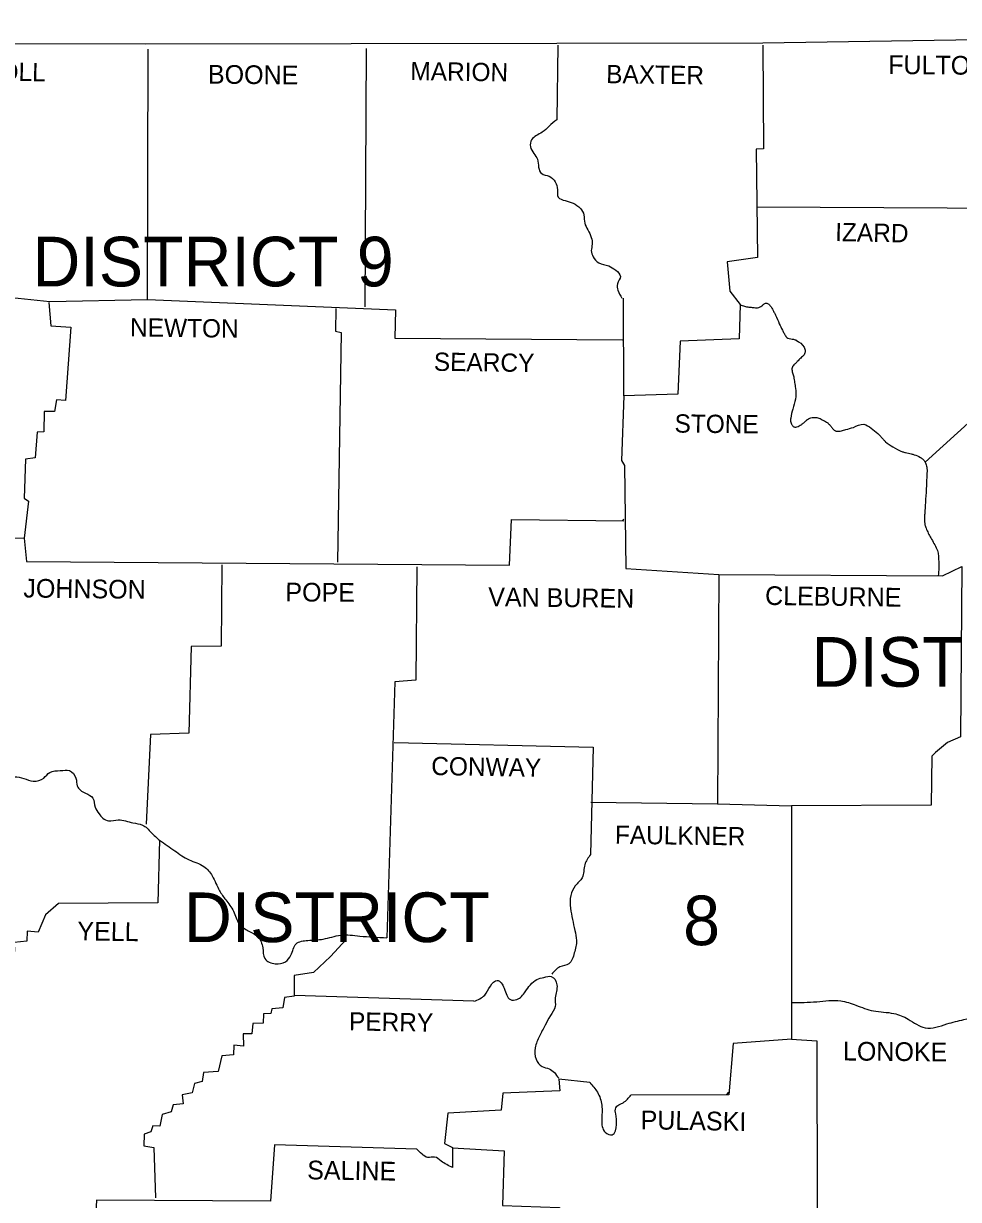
# Model space of a CAD drawing. Extents: x 3046 to 131673, y -8885 to 10756.
# Drawn here: x 103075 to 105176, y 7714 to 10358 of the extents above; entities that cross this region are included whole.
import ezdxf

# ---------------------------------------------------------------- set-up
doc = ezdxf.new("R2010")
doc.units = 0
for name, color, linetype in [('1', 7, 'Continuous'), ('2', 7, 'Continuous'), ('3', 7, 'Continuous')]:
    doc.layers.add(name, color=color, linetype=linetype)

msp = doc.modelspace()

# ---------------------------------------------------------------- linework, layer by layer
at = {"layer": '1'}
for points in [[(101766.1, 10313), (103348.2, 10312), (104736.6, 10314.9), (106374.4, 10340.4), (107133.7, 10358)], [(101766.1, 10313), (103348.2, 10312), (104736.6, 10314.9), (106374.4, 10340.4), (107133.7, 10358)], [(105565.2, 10327.8), (105567.2, 10081.1), (105440, 10074.3), (105436.1, 9941.2), (104723.5, 9945.1)], [(105565.2, 10327.8), (105567.2, 10081.1), (105440, 10074.3), (105436.1, 9941.2), (104723.5, 9945.1)], [(102667.2, 10007.7), (102907.9, 9999.9), (102913.8, 9968.6), (102947.1, 9967.6), (102946.1, 9948), (102969.6, 9942.2), (102971.5, 9835.5), (103001.9, 9828.7), (103003.8, 9786.6), (103046.9, 9780.7), (103048.8, 9741.6), (103133.9, 9732.8), (103353.1, 9737.7), (103355.1, 10300.3)], [(102667.2, 10007.7), (102907.9, 9999.9), (102913.8, 9968.6), (102947.1, 9967.6), (102946.1, 9948), (102969.6, 9942.2), (102971.5, 9835.5), (103001.9, 9828.7), (103003.8, 9786.6), (103046.9, 9780.7), (103048.8, 9741.6), (103133.9, 9732.8), (103353.1, 9737.7), (103355.1, 10300.3)], [(103845.2, 10302.2), (103842.3, 9721.1)], [(103845.2, 10302.2), (103842.3, 9721.1)], [(104275.7, 10309.1), (104273.8, 10141.8)], [(104275.7, 10309.1), (104273.8, 10141.8)], [(104736.6, 10309.1), (104738.5, 10076.2), (104721.9, 10075.2), (104724.8, 9831.6), (104656.3, 9821.8), (104662.2, 9756.3), (104685.7, 9725.9), (104683.7, 9648.7), (104550.7, 9643.8), (104545.8, 9524.4), (104424.5, 9520.5), (104418.6, 9375.7), (104425.4, 9363.9), (104428.4, 9133), (104637.7, 9119.3), (104634.8, 8603.7), (104801.1, 8598.8), (104801.1, 8074.4), (104670, 8064.6), (104660.3, 7949.2), (104440.1, 7948.2)], [(104736.6, 10309.1), (104738.5, 10076.2), (104721.9, 10075.2), (104724.8, 9831.6), (104656.3, 9821.8), (104662.2, 9756.3), (104685.7, 9725.9), (104683.7, 9648.7), (104550.7, 9643.8), (104545.8, 9524.4), (104424.5, 9520.5), (104418.6, 9375.7), (104425.4, 9363.9), (104428.4, 9133), (104637.7, 9119.3), (104634.8, 8603.7), (104801.1, 8598.8), (104801.1, 8074.4), (104670, 8064.6), (104660.3, 7949.2), (104440.1, 7948.2)], [(101843.4, 9721.1), (102026.4, 9720.1), (102031.3, 9784.6), (102098.8, 9784.6), (102104.7, 9889.3), (102486.2, 9875.6), (102498, 9905), (102655.5, 9906), (102576.2, 9679), (102560.6, 9316), (102548.9, 9315), (102543, 9205.4), (102600.7, 9200.5), (102609.5, 9209.3), (103076.2, 9200.5), (103081.1, 9148.7)], [(101843.4, 9721.1), (102026.4, 9720.1), (102031.3, 9784.6), (102098.8, 9784.6), (102104.7, 9889.3), (102486.2, 9875.6), (102498, 9905), (102655.5, 9906), (102576.2, 9679), (102560.6, 9316), (102548.9, 9315), (102543, 9205.4), (102600.7, 9200.5), (102609.5, 9209.3), (103076.2, 9200.5), (103081.1, 9148.7)], [(103132, 9730.8), (103135.9, 9678), (103180.9, 9675.1), (103169.2, 9510.7), (103148.6, 9511.7), (103144.7, 9485.3), (103121.2, 9485.3), (103120.2, 9440.2), (103105.6, 9439.3), (103100.7, 9381.5), (103079.1, 9378.6), (103076.2, 9290.6), (103086, 9283.7), (103076.2, 9200.5)], [(103132, 9730.8), (103135.9, 9678), (103180.9, 9675.1), (103169.2, 9510.7), (103148.6, 9511.7), (103144.7, 9485.3), (103121.2, 9485.3), (103120.2, 9440.2), (103105.6, 9439.3), (103100.7, 9381.5), (103079.1, 9378.6), (103076.2, 9290.6), (103086, 9283.7), (103076.2, 9200.5)], [(103353.1, 9737.7), (103910.8, 9714.2), (103909.8, 9650.6), (104421.5, 9646.7)], [(103353.1, 9737.7), (103910.8, 9714.2), (103909.8, 9650.6), (104421.5, 9646.7)], [(104424.5, 9520.5), (104423.5, 9740.6)], [(104424.5, 9520.5), (104423.5, 9740.6)], [(103776.8, 9717.1), (103775.8, 9666.3), (103788.5, 9663.3), (103780.7, 9146.7)], [(103776.8, 9717.1), (103775.8, 9666.3), (103788.5, 9663.3), (103780.7, 9146.7)], [(105101.4, 9371.9), (105215, 9474.5), (105567.2, 9469.6), (105574.1, 9404), (105703.2, 9409)], [(105101.4, 9371.9), (105215, 9474.5), (105567.2, 9469.6), (105574.1, 9404), (105703.2, 9409)], [(103081.1, 9148.7), (104167.1, 9139.9), (104172, 9242.6), (104424.5, 9239.7)], [(103081.1, 9148.7), (104167.1, 9139.9), (104172, 9242.6), (104424.5, 9239.7)], [(104421.5, 9240.7), (104424.5, 9243.6)], [(104421.5, 9240.7), (104424.5, 9243.6)], [(103520.4, 9140.9), (103519.4, 8957.9), (103451.9, 8956.9), (103446, 8762.2), (103359.9, 8759.3), (103350.2, 8557.7)], [(103520.4, 9140.9), (103519.4, 8957.9), (103451.9, 8956.9), (103446, 8762.2), (103359.9, 8759.3), (103350.2, 8557.7)], [(103958.7, 9136), (103956.8, 8881.6), (103909.8, 8877.7), (103891.2, 8302.4)], [(103958.7, 9136), (103956.8, 8881.6), (103909.8, 8877.7), (103891.2, 8302.4)], [(104637.7, 9119.3), (105140.6, 9116.4), (105183.7, 9136.9), (105180.8, 8754.4), (105151.4, 8741.7), (105125, 8719.2), (105116.2, 8710.4), (105115.2, 8600.8), (104801.1, 8598.8)], [(104637.7, 9119.3), (105140.6, 9116.4), (105183.7, 9136.9), (105180.8, 8754.4), (105151.4, 8741.7), (105125, 8719.2), (105116.2, 8710.4), (105115.2, 8600.8), (104801.1, 8598.8)], [(103907.9, 8741.7), (104355, 8730.9), (104349.1, 8489.2)], [(103907.9, 8741.7), (104355, 8730.9), (104349.1, 8489.2)], [(104350.1, 8607.6), (104634.8, 8603.7)], [(104350.1, 8607.6), (104634.8, 8603.7)], [(103380.5, 8521.5), (103376.6, 8380.6), (103153.5, 8379.7), (103124.2, 8354.2), (103107.5, 8315.1), (103083.1, 8317), (103082.1, 8294.5), (103053.7, 8291.6), (103054.7, 8271.1), (102912.8, 8275), (102907.9, 8259.3), (102849.2, 8257.4), (102847.3, 7685)], [(103380.5, 8521.5), (103376.6, 8380.6), (103153.5, 8379.7), (103124.2, 8354.2), (103107.5, 8315.1), (103083.1, 8317), (103082.1, 8294.5), (103053.7, 8291.6), (103054.7, 8271.1), (102912.8, 8275), (102907.9, 8259.3), (102849.2, 8257.4), (102847.3, 7685)], [(103800.2, 8298.4), (103765, 8260.3), (103726.9, 8224.1), (103682.8, 8217.2), (103682.8, 8171.3), (103661.3, 8168.3), (103657.4, 8144.8), (103632.9, 8142.9), (103631, 8132.1), (103614.3, 8131.1), (103613.4, 8110.6), (103589.9, 8109.6), (103587.9, 8086.1), (103568.4, 8086.1), (103569.3, 8058.7), (103547.8, 8060.7), (103546.8, 8039.2), (103520.4, 8037.2), (103512.6, 8002), (103479.3, 7999.1), (103476.4, 7979.5), (103458.8, 7974.6), (103453.9, 7954), (103431.4, 7949.2), (103433.3, 7928.6), (103410.8, 7926.7), (103406.9, 7911), (103386.4, 7905.1), (103381.5, 7878.7), (103365.8, 7879.7), (103360.9, 7866), (103346.3, 7861.1), (103345.3, 7834.7), (103367.8, 7830.8), (103371.7, 7717.3)], [(103800.2, 8298.4), (103765, 8260.3), (103726.9, 8224.1), (103682.8, 8217.2), (103682.8, 8171.3), (103661.3, 8168.3), (103657.4, 8144.8), (103632.9, 8142.9), (103631, 8132.1), (103614.3, 8131.1), (103613.4, 8110.6), (103589.9, 8109.6), (103587.9, 8086.1), (103568.4, 8086.1), (103569.3, 8058.7), (103547.8, 8060.7), (103546.8, 8039.2), (103520.4, 8037.2), (103512.6, 8002), (103479.3, 7999.1), (103476.4, 7979.5), (103458.8, 7974.6), (103453.9, 7954), (103431.4, 7949.2), (103433.3, 7928.6), (103410.8, 7926.7), (103406.9, 7911), (103386.4, 7905.1), (103381.5, 7878.7), (103365.8, 7879.7), (103360.9, 7866), (103346.3, 7861.1), (103345.3, 7834.7), (103367.8, 7830.8), (103371.7, 7717.3)], [(104086.9, 8159.5), (103683.8, 8172.2)], [(104086.9, 8159.5), (103683.8, 8172.2)], [(104801.1, 8074.4), (104857.9, 8070.5), (104858.9, 7696.7), (104808, 7484.4), (104916.6, 7479.5), (104915.6, 7292.5)], [(104801.1, 8074.4), (104857.9, 8070.5), (104858.9, 7696.7), (104808, 7484.4), (104916.6, 7479.5), (104915.6, 7292.5)], [(104348.1, 7976.6), (104277.7, 7984.4), (104280.6, 7958), (104152.5, 7953.1), (104148.5, 7914.9), (104028.2, 7908.1), (104021.4, 7839.6), (104039, 7830.8), (104039, 7785.8)], [(104348.1, 7976.6), (104277.7, 7984.4), (104280.6, 7958), (104152.5, 7953.1), (104148.5, 7914.9), (104028.2, 7908.1), (104021.4, 7839.6), (104039, 7830.8), (104039, 7785.8)], [(104655.4, 7950.1), (104660.3, 7955)], [(104655.4, 7950.1), (104660.3, 7955)], [(103958.7, 7826.9), (103638.8, 7836.6), (103630, 7710.4), (103238.6, 7712.4), (103236.7, 7670.3)], [(103958.7, 7826.9), (103638.8, 7836.6), (103630, 7710.4), (103238.6, 7712.4), (103236.7, 7670.3)], [(104039, 7830.2), (104155.4, 7822.9), (104151.5, 7700.6), (104279.7, 7695.8), (104281.6, 7589.1), (104342.3, 7584.2), (104342.3, 7565.6), (104399, 7561.7), (104401, 7493.2), (104530.1, 7493.2), (104534, 7425.7), (104653.4, 7419.8), (104652.4, 7292.5)], [(104039, 7830.2), (104155.4, 7822.9), (104151.5, 7700.6), (104279.7, 7695.8), (104281.6, 7589.1), (104342.3, 7584.2), (104342.3, 7565.6), (104399, 7561.7), (104401, 7493.2), (104530.1, 7493.2), (104534, 7425.7), (104653.4, 7419.8), (104652.4, 7292.5)]]:
    msp.add_lwpolyline(points, dxfattribs=at)
for points in [[(104273.8, 10141.8), (104256.2, 10127.1), (104240.5, 10113.4), (104217, 10096.8), (104214.1, 10081.1), (104221.9, 10065.5), (104229.8, 10052.7), (104232.7, 10035.1), (104239.5, 10020.4), (104256.2, 10014.6), (104269.9, 10001.9), (104274.8, 9984.2), (104276.7, 9967.6), (104292.4, 9959.8), (104310, 9953.9), (104326.6, 9942.2), (104334.4, 9927.5), (104336.4, 9908.9), (104343.2, 9894.2), (104351.1, 9876.6), (104353, 9861.9), (104351.1, 9847.3), (104355, 9833.6), (104367.7, 9819.9), (104390.2, 9813), (104405.9, 9803.2), (104416.6, 9789.5), (104409.8, 9772.9), (104410.8, 9758.2), (104419.6, 9740.6)], [(104273.8, 10141.8), (104256.2, 10127.1), (104240.5, 10113.4), (104217, 10096.8), (104214.1, 10081.1), (104221.9, 10065.5), (104229.8, 10052.7), (104232.7, 10035.1), (104239.5, 10020.4), (104256.2, 10014.6), (104269.9, 10001.9), (104274.8, 9984.2), (104276.7, 9967.6), (104292.4, 9959.8), (104310, 9953.9), (104326.6, 9942.2), (104334.4, 9927.5), (104336.4, 9908.9), (104343.2, 9894.2), (104351.1, 9876.6), (104353, 9861.9), (104351.1, 9847.3), (104355, 9833.6), (104367.7, 9819.9), (104390.2, 9813), (104405.9, 9803.2), (104416.6, 9789.5), (104409.8, 9772.9), (104410.8, 9758.2), (104419.6, 9740.6)], [(104685.7, 9725.9), (104695.3, 9722.3), (104705.1, 9720.3), (104715, 9719.5), (104724.8, 9719.1), (104730.9, 9721.1), (104737, 9725.5), (104742.8, 9728.9), (104745.6, 9729.2), (104748.3, 9727.9), (104753.9, 9722.3), (104758.2, 9716), (104761.7, 9709.3), (104764.9, 9702.5), (104773.7, 9682.9), (104780.5, 9668.5), (104784.3, 9661.4), (104786.3, 9657.9), (104788.4, 9654.5), (104793, 9650.8), (104799.2, 9649.2), (104805.8, 9648), (104809, 9647.1), (104811.9, 9645.7), (104829.5, 9630.1), (104832, 9621.6), (104831.4, 9617.2), (104829.5, 9613.4), (104825.8, 9609.4), (104821.8, 9605.6), (104817.7, 9601.8), (104813.9, 9597.8), (104812.1, 9595.9), (104806.5, 9590.4), (104803.5, 9586.5), (104802.6, 9584.4), (104802.1, 9582.1), (104802.4, 9577.5), (104803.5, 9572.9), (104804.9, 9568.2), (104806, 9563.5), (104808.1, 9550.8), (104809.9, 9538.1), (104809.9, 9513.6), (104804.1, 9491.1), (104799.2, 9470.6), (104798.7, 9466.1), (104799.3, 9461.7), (104801.1, 9457.3), (104802.4, 9455.1), (104804.1, 9453), (104806.1, 9451.3), (104808.3, 9450.5), (104813.3, 9451.2), (104822.7, 9455.9), (104827.6, 9459.4), (104832.2, 9463.6), (104837, 9467.7), (104842.2, 9470.6), (104847.2, 9471.8), (104852.5, 9472.3), (104862.8, 9470.6), (104872.8, 9465.7), (104882.4, 9459.8), (104887.6, 9454.9), (104892.2, 9449), (104897.1, 9443.8), (104899.8, 9442.1), (104901.3, 9441.5), (104902.9, 9441.2), (104913.1, 9442.2), (104923.4, 9445.1), (104940.1, 9450), (104963.6, 9456.9), (104980.2, 9448.1), (104994.9, 9436.3), (104999.4, 9431.8), (105003.6, 9427), (105007.9, 9422.2), (105012.5, 9417.7), (105029.1, 9406), (105050.6, 9395.2), (105057.1, 9393.1), (105063.7, 9391.7), (105070.4, 9390.3), (105077.1, 9388.4), (105090.9, 9382.4), (105096.9, 9377.9), (105099.4, 9375.1), (105100.5, 9373.5), (105101.5, 9371.8), (105103.1, 9368.2), (105105.5, 9357.6), (105105.7, 9350.5), (105105.4, 9343.4), (105104.4, 9318.9), (105102.5, 9288.6), (105100.5, 9255.3), (105100.1, 9247.2), (105100.2, 9239.1), (105101.1, 9231), (105102.1, 9227), (105103.5, 9223), (105108.6, 9212), (105114.2, 9201.5), (105121.2, 9189), (105127.9, 9176.1), (105131, 9164.5), (105131.5, 9158.6), (105131.8, 9152.6), (105132.3, 9134.5), (105131, 9116.5)], [(104685.7, 9725.9), (104695.3, 9722.3), (104705.1, 9720.3), (104715, 9719.5), (104724.8, 9719.1), (104730.9, 9721.1), (104737, 9725.5), (104742.8, 9728.9), (104745.6, 9729.2), (104748.3, 9727.9), (104753.9, 9722.3), (104758.2, 9716), (104761.7, 9709.3), (104764.9, 9702.5), (104773.7, 9682.9), (104780.5, 9668.5), (104784.3, 9661.4), (104786.3, 9657.9), (104788.4, 9654.5), (104793, 9650.8), (104799.2, 9649.2), (104805.8, 9648), (104809, 9647.1), (104811.9, 9645.7), (104829.5, 9630.1), (104832, 9621.6), (104831.4, 9617.2), (104829.5, 9613.4), (104825.8, 9609.4), (104821.8, 9605.6), (104817.7, 9601.8), (104813.9, 9597.8), (104812.1, 9595.9), (104806.5, 9590.4), (104803.5, 9586.5), (104802.6, 9584.4), (104802.1, 9582.1), (104802.4, 9577.5), (104803.5, 9572.9), (104804.9, 9568.2), (104806, 9563.5), (104808.1, 9550.8), (104809.9, 9538.1), (104809.9, 9513.6), (104804.1, 9491.1), (104799.2, 9470.6), (104798.7, 9466.1), (104799.3, 9461.7), (104801.1, 9457.3), (104802.4, 9455.1), (104804.1, 9453), (104806.1, 9451.3), (104808.3, 9450.5), (104813.3, 9451.2), (104822.7, 9455.9), (104827.6, 9459.4), (104832.2, 9463.6), (104837, 9467.7), (104842.2, 9470.6), (104847.2, 9471.8), (104852.5, 9472.3), (104862.8, 9470.6), (104872.8, 9465.7), (104882.4, 9459.8), (104887.6, 9454.9), (104892.2, 9449), (104897.1, 9443.8), (104899.8, 9442.1), (104901.3, 9441.5), (104902.9, 9441.2), (104913.1, 9442.2), (104923.4, 9445.1), (104940.1, 9450), (104963.6, 9456.9), (104980.2, 9448.1), (104994.9, 9436.3), (104999.4, 9431.8), (105003.6, 9427), (105007.9, 9422.2), (105012.5, 9417.7), (105029.1, 9406), (105050.6, 9395.2), (105057.1, 9393.1), (105063.7, 9391.7), (105070.4, 9390.3), (105077.1, 9388.4), (105090.9, 9382.4), (105096.9, 9377.9), (105099.4, 9375.1), (105100.5, 9373.5), (105101.5, 9371.8), (105103.1, 9368.2), (105105.5, 9357.6), (105105.7, 9350.5), (105105.4, 9343.4), (105104.4, 9318.9), (105102.5, 9288.6), (105100.5, 9255.3), (105100.1, 9247.2), (105100.2, 9239.1), (105101.1, 9231), (105102.1, 9227), (105103.5, 9223), (105108.6, 9212), (105114.2, 9201.5), (105121.2, 9189), (105127.9, 9176.1), (105131, 9164.5), (105131.5, 9158.6), (105131.8, 9152.6), (105132.3, 9134.5), (105131, 9116.5)], [(102863.9, 8639.9), (102896.2, 8650.7), (102919.7, 8652.6), (102943.1, 8648.7), (102967.6, 8638.9), (102994, 8640.9), (103013.6, 8647.7), (103033.2, 8660.5), (103054.7, 8664.4), (103075.2, 8660.5), (103096.8, 8654.6), (103120.2, 8661.4), (103133.9, 8674.2), (103157.4, 8678.1), (103178, 8678.1), (103192.6, 8661.4), (103195.6, 8643.8), (103214.2, 8627.2), (103230.8, 8616.4), (103235.7, 8595.9), (103244.5, 8581.2), (103253.3, 8571.4), (103266, 8565.6), (103287.5, 8567.5), (103320.8, 8560.7), (103342.3, 8555.8), (103361.9, 8539.1), (103380.5, 8521.5)], [(102863.9, 8639.9), (102896.2, 8650.7), (102919.7, 8652.6), (102943.1, 8648.7), (102967.6, 8638.9), (102994, 8640.9), (103013.6, 8647.7), (103033.2, 8660.5), (103054.7, 8664.4), (103075.2, 8660.5), (103096.8, 8654.6), (103120.2, 8661.4), (103133.9, 8674.2), (103157.4, 8678.1), (103178, 8678.1), (103192.6, 8661.4), (103195.6, 8643.8), (103214.2, 8627.2), (103230.8, 8616.4), (103235.7, 8595.9), (103244.5, 8581.2), (103253.3, 8571.4), (103266, 8565.6), (103287.5, 8567.5), (103320.8, 8560.7), (103342.3, 8555.8), (103361.9, 8539.1), (103380.5, 8521.5)], [(103380.5, 8521.5), (103414.7, 8498), (103447, 8477.5), (103480.3, 8462.8), (103498.9, 8441.3), (103515.5, 8408), (103529.2, 8387.5), (103546.8, 8362), (103559.5, 8333.7), (103580.1, 8318), (103601.6, 8304.3), (103612.4, 8279.9), (103617.3, 8255.4), (103640.8, 8243.7), (103663.3, 8248.5), (103676, 8263.2), (103687.7, 8288.7), (103714.1, 8296.5), (103748.4, 8299.4), (103787.5, 8308.2), (103830.6, 8306.3), (103891.2, 8302.4)], [(103380.5, 8521.5), (103414.7, 8498), (103447, 8477.5), (103480.3, 8462.8), (103498.9, 8441.3), (103515.5, 8408), (103529.2, 8387.5), (103546.8, 8362), (103559.5, 8333.7), (103580.1, 8318), (103601.6, 8304.3), (103612.4, 8279.9), (103617.3, 8255.4), (103640.8, 8243.7), (103663.3, 8248.5), (103676, 8263.2), (103687.7, 8288.7), (103714.1, 8296.5), (103748.4, 8299.4), (103787.5, 8308.2), (103830.6, 8306.3), (103891.2, 8302.4)], [(104349.1, 8489.2), (104336.4, 8466.7), (104330.5, 8437.4), (104314.9, 8418.8), (104305.1, 8397.3), (104304.1, 8368.9), (104309, 8343.5), (104313.9, 8319), (104317.8, 8296.5), (104312.9, 8268.1), (104300.2, 8243.7), (104280.6, 8236.8), (104262, 8220.2)], [(104349.1, 8489.2), (104336.4, 8466.7), (104330.5, 8437.4), (104314.9, 8418.8), (104305.1, 8397.3), (104304.1, 8368.9), (104309, 8343.5), (104313.9, 8319), (104317.8, 8296.5), (104312.9, 8268.1), (104300.2, 8243.7), (104280.6, 8236.8), (104262, 8220.2)], [(104086.9, 8159.5), (104111.4, 8173.2), (104124.1, 8193.8), (104139.7, 8206.5), (104155.4, 8188.9), (104169.1, 8163.4), (104183.8, 8163.4), (104202.4, 8181), (104214.1, 8196.7), (104228.8, 8208.4), (104244.4, 8213.3), (104261.1, 8215.3), (104273.8, 8196.7), (104269.9, 8167.3), (104269.9, 8147.8), (104259.1, 8127.2), (104247.4, 8105.7), (104234.6, 8081.2), (104224.9, 8054.8), (104226.8, 8029.4), (104240.5, 8012.8), (104256.2, 8007.9), (104277.7, 7986.3)], [(104086.9, 8159.5), (104111.4, 8173.2), (104124.1, 8193.8), (104139.7, 8206.5), (104155.4, 8188.9), (104169.1, 8163.4), (104183.8, 8163.4), (104202.4, 8181), (104214.1, 8196.7), (104228.8, 8208.4), (104244.4, 8213.3), (104261.1, 8215.3), (104273.8, 8196.7), (104269.9, 8167.3), (104269.9, 8147.8), (104259.1, 8127.2), (104247.4, 8105.7), (104234.6, 8081.2), (104224.9, 8054.8), (104226.8, 8029.4), (104240.5, 8012.8), (104256.2, 8007.9), (104277.7, 7986.3)], [(104800.7, 8156.5), (104857.9, 8158.5), (104911.7, 8160.5), (104945.9, 8150.7), (104985.1, 8138), (105031.1, 8132.1), (105063.4, 8119.4), (105101.5, 8099.8), (105150.4, 8108.6), (105188.6, 8118.4), (105238.5, 8131.1), (105270.8, 8144.8), (105308, 8156.6), (105345.1, 8151.7), (105387.2, 8143.9), (105413.6, 8128.2), (105461.6, 8135.1), (105461.6, 8195.7)], [(104800.7, 8156.5), (104857.9, 8158.5), (104911.7, 8160.5), (104945.9, 8150.7), (104985.1, 8138), (105031.1, 8132.1), (105063.4, 8119.4), (105101.5, 8099.8), (105150.4, 8108.6), (105188.6, 8118.4), (105238.5, 8131.1), (105270.8, 8144.8), (105308, 8156.6), (105345.1, 8151.7), (105387.2, 8143.9), (105413.6, 8128.2), (105461.6, 8135.1), (105461.6, 8195.7)], [(104348.1, 7976.6), (104364.8, 7955), (104374.6, 7925.7), (104374.6, 7892.4), (104382.4, 7865), (104398, 7859.1), (104407.8, 7882.6), (104405.9, 7906.1), (104405.9, 7919.8), (104422.5, 7931.5), (104440.1, 7948.2)], [(104348.1, 7976.6), (104364.8, 7955), (104374.6, 7925.7), (104374.6, 7892.4), (104382.4, 7865), (104398, 7859.1), (104407.8, 7882.6), (104405.9, 7906.1), (104405.9, 7919.8), (104422.5, 7931.5), (104440.1, 7948.2)], [(104039, 7785.8), (104013.5, 7800.4), (103998.8, 7809.2), (103983.2, 7808.3), (103970.5, 7816.1), (103958.7, 7826.9)], [(104039, 7785.8), (104013.5, 7800.4), (103998.8, 7809.2), (103983.2, 7808.3), (103970.5, 7816.1), (103958.7, 7826.9)]]:
    msp.add_spline(points, degree=3, dxfattribs=at)

# ---------------------------------------------------------------- texts
at = {"layer": '2'}
for s, height, rotation, p in [('FULTON', 42.06, 359.4996, (105018.3, 10244.5)), ('FULTON', 42.06, 359.4996, (105018.3, 10244.5)), ('CARROLL', 41.09, 359.1481, (102864.9, 10231.8)), ('CARROLL', 41.09, 359.1481, (102864.9, 10231.8)), ('BOONE', 42.07, 359.4001, (103489.1, 10223)), ('BOONE', 42.07, 359.4001, (103489.1, 10223)), ('MARION', 41.09, 359.1854, (103944.1, 10230.8)), ('MARION', 41.09, 359.1854, (103944.1, 10230.8)), ('BAXTER', 41.09, 359.2559, (104384.3, 10224)), ('BAXTER', 41.09, 359.2559, (104384.3, 10224)), ('IZARD', 41.08, 358.9258, (104899, 9868.8)), ('IZARD', 41.08, 358.9258, (104899, 9868.8)), ('NEWTON', 41.09, 359.2717, (103314, 9654.5)), ('NEWTON', 41.09, 359.2717, (103314, 9654.5)), ('SEARCY', 41.08, 359.2527, (103996.9, 9577.2)), ('SEARCY', 41.08, 359.2527, (103996.9, 9577.2)), ('STONE', 41.08, 359.4001, (104538, 9438.3)), ('STONE', 41.08, 359.4001, (104538, 9438.3)), ('JOHNSON', 42.07, 359.3514, (103074.3, 9067.5)), ('JOHNSON', 42.07, 359.3514, (103074.3, 9067.5)), ('POPE', 42.07, 359.6155, (103663.3, 9058.7)), ('POPE', 42.07, 359.6155, (103663.3, 9058.7)), ('VAN BUREN', 42.07, 359.3508, (104119.2, 9047.9)), ('VAN BUREN', 42.07, 359.3508, (104119.2, 9047.9)), ('CLEBURNE', 42.06, 359.2535, (104741.5, 9050.8)), ('CLEBURNE', 42.06, 359.2535, (104741.5, 9050.8)), ('CONWAY', 41.08, 359.0371, (103991, 8668.3)), ('CONWAY', 41.08, 359.0371, (103991, 8668.3)), ('FAULKNER', 41.09, 359.2486, (104403.9, 8513.7)), ('FAULKNER', 41.09, 359.2486, (104403.9, 8513.7)), ('YELL', 42.07, 359.1987, (103195.6, 8296.5)), ('YELL', 42.07, 359.1987, (103195.6, 8296.5)), ('PERRY', 41.09, 359.0858, (103806.1, 8094)), ('PERRY', 41.09, 359.0858, (103806.1, 8094)), ('LONOKE', 42.07, 359.4974, (104916.6, 8026.5)), ('LONOKE', 42.07, 359.4974, (104916.6, 8026.5)), ('PULASKI', 42.07, 359.053, (104461.6, 7871.9)), ('PULASKI', 42.07, 359.053, (104461.6, 7871.9)), ('SALINE', 42.07, 359.1491, (103712.2, 7759.3)), ('SALINE', 42.07, 359.1491, (103712.2, 7759.3))]:
    msp.add_text(s, height=height, rotation=rotation, dxfattribs=at).set_placement(p)
at = {"layer": '3'}
for s, height, p in [('DISTRICT 9', 111.54, (103094.8, 9767)), ('DISTRICT 9', 111.54, (103094.8, 9767)), ('DISTRICT', 111.54, (104846.1, 8866.9)), ('DISTRICT', 111.54, (104846.1, 8866.9)), ('DISTRICT', 111.54, (103435.3, 8292.6)), ('DISTRICT', 111.54, (103435.3, 8292.6)), ('8', 111.5, (104557.5, 8285.7)), ('8', 111.5, (104557.5, 8285.7))]:
    msp.add_text(s, height=height, dxfattribs=at).set_placement(p)

doc.saveas('drawing.dxf')
